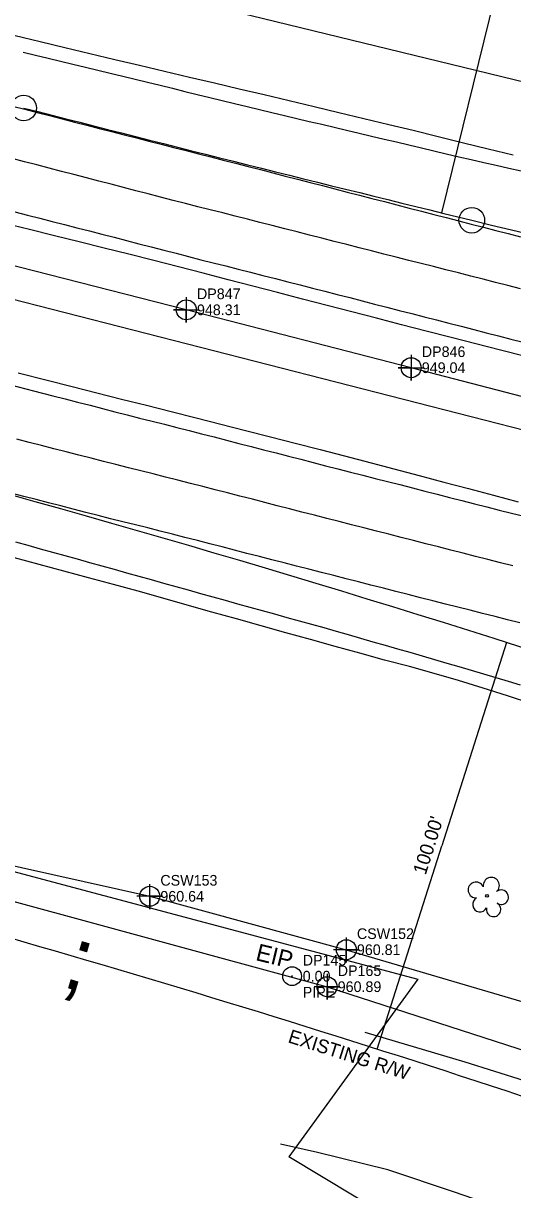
# Model space of a CAD drawing. Extents: x 1182322 to 1186765, y 572295 to 575411.
# Drawn here: x 1183432.3 to 1183547, y 574148.9 to 574422.2 of the extents above; entities that cross this region are included whole.
import ezdxf

# ---------------------------------------------------------------- set-up
doc = ezdxf.new("R2010")
doc.units = 0
for name, color, linetype in [('COGO Default Chain', 7, 'Continuous'), ('Exist Guardrail Cable Guide Rail', 7, 'Continuous'), ('Exist Guardrail Cable Guide Rail Cogo Elevation', 7, 'Continuous'), ('Exist Guardrail Cable Guide Rail Cogo Number', 7, 'Continuous'), ('Exist Guardrail Cable Guide Rail Cogo Point CELL', 7, 'Continuous'), ('Exist Horizontal Alignment', 7, 'Continuous'), ('Exist Horizontal Alignment Point', 7, 'Continuous'), ('Exist Other Culture Fence Line', 7, 'Continuous'), ('Exist Other Culture Fence Line Cogo Elevation', 7, 'Continuous'), ('Exist Other Culture Fence Line Cogo Number', 7, 'Continuous'), ('Exist Other Culture Fence Line Cogo Point CELL', 7, 'Continuous'), ('Exist Property Iron Pin CELL', 7, 'Continuous'), ('Exist Property Iron Pin Cogo Comment', 7, 'Continuous'), ('Exist Property Iron Pin Cogo Elevation', 7, 'Continuous'), ('Exist Property Iron Pin Cogo Number', 7, 'Continuous'), ('Exist Property Iron Pin Text', 7, 'Continuous'), ('Exist Right of Way Control of Access CA Symbol CELL', 7, 'Continuous'), ('Exist Right of Way Line', 7, 'Continuous'), ('Exist Right of Way Line Text', 7, 'Continuous'), ('Exist Right of Way Width CELL', 7, 'Continuous'), ('Exist Roads EOP', 7, 'Continuous'), ('Exist Roads EOT', 7, 'Continuous'), ('Exist Roads Soil', 7, 'Continuous'), ('Exist Structure Minor Pipes RCP 18 Inch', 7, 'Continuous'), ('Exist Utilities Telephone UG Conduit SUE LOS B', 7, 'Continuous'), ('Exist Utilities Telephone UG Conduit SUE LOS B Cogo Elevation', 7, 'Continuous'), ('Exist Utilities Telephone UG Conduit SUE LOS B Cogo Number', 7, 'Continuous'), ('Exist Utilities Telephone UG Conduit SUE LOS B Cogo Point CELL', 7, 'Continuous'), ('Exist Vegetation Tree CELL', 7, 'Continuous'), ('Sheet Layout Plan Border', 7, 'Continuous')]:
    doc.layers.add(name, color=color, linetype=linetype)

msp = doc.modelspace()

# ---------------------------------------------------------------- linework, layer by layer
at = {"layer": 'COGO Default Chain'}
msp.add_line((1182528.88, 574588.22), (1185362.14, 573862.9), dxfattribs=at)
for centre, radius, start, end in [((1186009.24, 584468.11), 10390.38, 255.640516, 256.23755), ((1183890.06, 575815.87), 1482.39, 256.23755, 268.02702), ((1182574.75, 571226.37), 3201.45, 68.49303, 75.64052)]:
    msp.add_arc(centre, radius, start, end, dxfattribs=at)
at = {"layer": 'Exist Guardrail Cable Guide Rail'}
msp.add_lwpolyline([(1183724.74, 574289.7), (1183677.28, 574301.88), (1183623.6, 574315.48), (1183573.41, 574328.42), (1183523.18, 574341.49), (1183470.48, 574355.05), (1183416.85, 574368.69), (1183366.96, 574381.41), (1183314.88, 574394.83), (1183262.33, 574408.3), (1183212.68, 574421.31), (1183161.26, 574434.27), (1183113.83, 574446.38), (1183064.43, 574459.18), (1183012.5, 574472.56), (1182962.1, 574485.47), (1182911.03, 574498.69), (1182859.7, 574511.98), (1182808.96, 574524.96), (1182757.01, 574537.77), (1182704.44, 574551.53), (1182655.16, 574564.04), (1182603.29, 574577.2), (1182552.65, 574589.83)], dxfattribs=at)
at = {"layer": 'Exist Guardrail Cable Guide Rail Cogo Point CELL'}
for points in [[(1183470.48, 574358.05), (1183470.48, 574352.05), (1183470.48, 574355.05), (1183467.48, 574355.05), (1183473.48, 574355.05)], [(1183523.18, 574344.49), (1183523.18, 574338.49), (1183523.18, 574341.49), (1183520.18, 574341.49), (1183526.18, 574341.49)]]:
    msp.add_lwpolyline(points, dxfattribs=at)
for centre in [(1183470.48, 574355.05), (1183523.18, 574341.49)]:
    msp.add_circle(centre, 2.34, dxfattribs=at)
at = {"layer": 'Exist Horizontal Alignment'}
msp.add_line((1182528.88, 574588.22), (1185362.14, 573862.9), dxfattribs=at)
for centre, radius, start, end in [((1186009.24, 584468.11), 10390.38, 255.640516, 256.23755), ((1183890.06, 575815.87), 1482.39, 256.23755, 268.02702), ((1182574.75, 571226.37), 3201.45, 68.49303, 75.64052)]:
    msp.add_arc(centre, radius, start, end, dxfattribs=at)
at = {"layer": 'Exist Horizontal Alignment Point'}
for centre in [(1183432.37, 574402.34), (1183537.4, 574376.04)]:
    msp.add_circle(centre, 3, dxfattribs=at)
at = {"layer": 'Exist Other Culture Fence Line'}
msp.add_lwpolyline([(1182431.26, 574477.6), (1182493.19, 574461.53), (1182576.37, 574440.23), (1182660.35, 574418.61), (1182745.71, 574396.94), (1182831.35, 574374.93), (1182917.06, 574353.23), (1182998.89, 574331.88), (1183080.06, 574310.08), (1183166.11, 574287.18), (1183252.15, 574263.83), (1183335.82, 574241.7), (1183417.69, 574219.73), (1183503.47, 574196.43), (1183592.65, 574167.54), (1183679.28, 574135.7), (1183764.86, 574099.44), (1183841.01, 574057.63), (1183931.32, 574004.09)], dxfattribs=at)
at = {"layer": 'Exist Other Culture Fence Line Cogo Point CELL'}
msp.add_lwpolyline([(1183503.47, 574199.43), (1183503.47, 574193.43), (1183503.47, 574196.43), (1183506.47, 574196.43), (1183500.47, 574196.43)], dxfattribs=at)
msp.add_circle((1183503.47, 574196.43), 2.34, dxfattribs=at)
at = {"layer": 'Exist Property Iron Pin CELL'}
for radius in [2.2, 0.0707]:
    msp.add_circle((1183495.27, 574198.89), radius, dxfattribs=at)
at = {"layer": 'Exist Right of Way Control of Access CA Symbol CELL'}
msp.add_line((1183450.28, 574201.67), (1183450.28, 574201.67), dxfattribs=at)
at = {"layer": 'Exist Right of Way Line'}
msp.add_arc((1182574.75, 571226.37), 3101.45, 71.1212, 75.64052, dxfattribs=at)
at = {"layer": 'Exist Right of Way Width CELL'}
for p, q in [((1183530.41, 574377.75), (1183543.63, 574431.59)), ((1183545.56, 574277.07), (1183530.4, 574229.44)), ((1183515.23, 574181.78), (1183530.4, 574229.44))]:
    msp.add_line(p, q, dxfattribs=at)
at = {"layer": 'Exist Roads EOP'}
for points in [[(1183430.34, 574419.3), (1183436.2, 574417.91), (1183442.04, 574416.52), (1183447.87, 574415.13), (1183453.71, 574413.74), (1183459.55, 574412.36), (1183465.39, 574410.98), (1183471.23, 574409.61), (1183477.07, 574408.23), (1183482.91, 574406.86), (1183488.75, 574405.48), (1183494.59, 574404.1), (1183500.42, 574402.7), (1183506.25, 574401.31), (1183512.08, 574399.91), (1183517.92, 574398.51), (1183523.66, 574397.12), (1183529.55, 574395.67), (1183535.44, 574394.22), (1183541.23, 574392.8), (1183547.06, 574391.4)], [(1183549.98, 574344.13), (1183544.16, 574345.62), (1183538.35, 574347.11), (1183532.54, 574348.59), (1183526.73, 574350.08), (1183520.91, 574351.56), (1183515.1, 574353.06), (1183509.3, 574354.56), (1183503.49, 574356.07), (1183497.68, 574357.58), (1183491.88, 574359.09), (1183486.07, 574360.6), (1183480.26, 574362.11), (1183474.46, 574363.62), (1183468.65, 574365.13), (1183462.84, 574366.63), (1183457.02, 574368.08), (1183451.19, 574369.52), (1183445.37, 574370.96), (1183439.55, 574372.4), (1183433.72, 574373.84), (1183427.9, 574375.29)], [(1183431.1, 574340.32), (1183437.89, 574338.59), (1183443.7, 574337.1), (1183449.51, 574335.61), (1183455.33, 574334.14), (1183461.14, 574332.68), (1183466.96, 574331.21), (1183472.78, 574329.73), (1183478.59, 574328.25), (1183484.39, 574326.76), (1183490.19, 574325.28), (1183496, 574323.8), (1183501.82, 574322.31), (1183507.6, 574320.83), (1183513.8, 574319.22), (1183519.1, 574317.81), (1183525.07, 574316.22), (1183530.84, 574314.69), (1183536.65, 574313.14), (1183542.45, 574311.6), (1183548.25, 574310.07)], [(1183551.47, 574262.74), (1183545.76, 574264.59), (1183540.04, 574266.4), (1183534.31, 574268.17), (1183528.55, 574269.85), (1183522.76, 574271.43), (1183516.96, 574272.98), (1183511.18, 574274.57), (1183505.4, 574276.17), (1183499.61, 574277.77), (1183493.83, 574279.36), (1183488.05, 574280.97), (1183482.27, 574282.6), (1183476.5, 574284.22), (1183470.72, 574285.84), (1183464.95, 574287.47), (1183459.17, 574289.09), (1183453.38, 574290.66), (1183447.59, 574292.23), (1183441.8, 574293.79), (1183436, 574295.36), (1183430.21, 574296.93)]]:
    msp.add_lwpolyline(points, dxfattribs=at)
at = {"layer": 'Exist Roads EOT'}
for points in [[(1183432.25, 574415.45), (1183435.16, 574414.74), (1183438.08, 574414.03), (1183440.99, 574413.31), (1183443.9, 574412.59), (1183446.82, 574411.88), (1183449.73, 574411.18), (1183452.65, 574410.48), (1183455.57, 574409.78), (1183458.49, 574409.08), (1183461.4, 574408.37), (1183464.32, 574407.67), (1183467.23, 574406.97), (1183470.15, 574406.25), (1183473.06, 574405.54), (1183475.98, 574404.83), (1183478.89, 574404.13), (1183481.81, 574403.42), (1183484.73, 574402.72), (1183487.64, 574402.02), (1183490.56, 574401.32), (1183493.48, 574400.62), (1183496.4, 574399.92), (1183499.31, 574399.22), (1183502.23, 574398.53), (1183505.15, 574397.83), (1183508.07, 574397.14), (1183510.99, 574396.45), (1183513.91, 574395.76), (1183516.83, 574395.07), (1183519.75, 574394.38), (1183522.67, 574393.7), (1183525.59, 574393.01), (1183528.51, 574392.32), (1183531.43, 574391.63), (1183534.35, 574390.94), (1183537.27, 574390.27), (1183540.2, 574389.6), (1183543.12, 574388.93), (1183546.05, 574388.27), (1183548.97, 574387.61)], [(1183429.73, 574402.79), (1183432.64, 574402.04), (1183435.54, 574401.29), (1183438.45, 574400.55), (1183441.35, 574399.8), (1183444.26, 574399.05), (1183447.16, 574398.31), (1183450.07, 574397.57), (1183452.98, 574396.83), (1183455.88, 574396.08), (1183458.79, 574395.34), (1183461.7, 574394.6), (1183464.6, 574393.86), (1183467.51, 574393.11), (1183470.42, 574392.37), (1183473.32, 574391.63), (1183476.23, 574390.88), (1183479.14, 574390.14), (1183482.04, 574389.4), (1183484.95, 574388.66), (1183487.86, 574387.91), (1183490.76, 574387.16), (1183493.67, 574386.41), (1183496.57, 574385.66), (1183499.48, 574384.91), (1183502.38, 574384.16), (1183505.28, 574383.41), (1183508.19, 574382.66), (1183511.09, 574381.91), (1183514, 574381.16), (1183516.9, 574380.41), (1183519.81, 574379.66), (1183522.71, 574378.91), (1183525.62, 574378.16), (1183528.52, 574377.41), (1183531.43, 574376.66), (1183534.33, 574375.91), (1183537.23, 574375.15), (1183540.14, 574374.4), (1183543.04, 574373.65), (1183545.95, 574372.9), (1183548.85, 574372.14)], [(1183548.78, 574359.97), (1183545.87, 574360.72), (1183542.97, 574361.46), (1183540.06, 574362.21), (1183537.15, 574362.95), (1183534.25, 574363.69), (1183531.34, 574364.43), (1183528.43, 574365.17), (1183525.52, 574365.91), (1183522.62, 574366.64), (1183519.71, 574367.38), (1183516.8, 574368.12), (1183513.89, 574368.86), (1183510.99, 574369.6), (1183508.08, 574370.34), (1183505.17, 574371.08), (1183502.26, 574371.82), (1183499.36, 574372.56), (1183496.45, 574373.3), (1183493.54, 574374.04), (1183490.64, 574374.78), (1183487.73, 574375.52), (1183484.82, 574376.26), (1183481.91, 574377), (1183479.01, 574377.74), (1183476.1, 574378.48), (1183473.19, 574379.22), (1183470.28, 574379.96), (1183467.38, 574380.7), (1183464.47, 574381.44), (1183461.57, 574382.2), (1183458.66, 574382.95), (1183455.76, 574383.71), (1183452.86, 574384.46), (1183449.95, 574385.22), (1183447.05, 574385.97), (1183444.15, 574386.73), (1183441.24, 574387.48), (1183438.34, 574388.24), (1183435.44, 574388.99), (1183432.53, 574389.75), (1183429.63, 574390.5)], [(1183430.32, 574377.98), (1183433.22, 574377.24), (1183436.13, 574376.5), (1183439.04, 574375.76), (1183441.94, 574375.02), (1183444.85, 574374.27), (1183447.76, 574373.53), (1183450.66, 574372.79), (1183453.57, 574372.04), (1183456.47, 574371.29), (1183459.38, 574370.55), (1183462.28, 574369.8), (1183465.19, 574369.04), (1183468.09, 574368.29), (1183471, 574367.54), (1183473.9, 574366.8), (1183476.81, 574366.06), (1183479.72, 574365.33), (1183482.63, 574364.59), (1183485.53, 574363.85), (1183488.44, 574363.11), (1183491.35, 574362.37), (1183494.26, 574361.63), (1183497.17, 574360.89), (1183500.07, 574360.15), (1183502.98, 574359.4), (1183505.88, 574358.65), (1183508.79, 574357.91), (1183511.69, 574357.16), (1183514.6, 574356.41), (1183517.5, 574355.67), (1183520.41, 574354.92), (1183523.31, 574354.17), (1183526.22, 574353.42), (1183529.13, 574352.68), (1183532.03, 574351.93), (1183534.94, 574351.19), (1183537.84, 574350.44), (1183540.75, 574349.69), (1183543.65, 574348.93), (1183546.56, 574348.18), (1183549.46, 574347.44)], [(1183429.27, 574337.44), (1183434.65, 574336.06), (1183439.2, 574334.91), (1183442.11, 574334.16), (1183445.01, 574333.42), (1183447.92, 574332.67), (1183450.82, 574331.93), (1183453.73, 574331.18), (1183456.64, 574330.44), (1183459.54, 574329.69), (1183462.45, 574328.96), (1183465.36, 574328.23), (1183468.27, 574327.5), (1183471.18, 574326.76), (1183474.08, 574326.01), (1183476.99, 574325.26), (1183479.89, 574324.51), (1183482.8, 574323.76), (1183485.7, 574323.01), (1183488.61, 574322.27), (1183491.51, 574321.52), (1183494.42, 574320.77), (1183497.32, 574320.02), (1183500.23, 574319.27), (1183503.13, 574318.51), (1183506.03, 574317.76), (1183508.94, 574317.01), (1183511.85, 574316.28), (1183514.76, 574315.55), (1183517.67, 574314.82), (1183520.57, 574314.08), (1183523.48, 574313.33), (1183526.38, 574312.58), (1183529.29, 574311.83), (1183532.2, 574311.09), (1183535.1, 574310.34), (1183538.01, 574309.59), (1183540.92, 574308.86), (1183543.83, 574308.13), (1183546.74, 574307.4), (1183549.64, 574306.66)], [(1183547.01, 574295.04), (1183544.1, 574295.78), (1183541.19, 574296.52), (1183538.29, 574297.26), (1183535.38, 574298), (1183532.47, 574298.74), (1183529.56, 574299.48), (1183526.66, 574300.22), (1183523.75, 574300.97), (1183520.84, 574301.71), (1183517.94, 574302.45), (1183515.03, 574303.19), (1183512.12, 574303.93), (1183509.22, 574304.68), (1183506.31, 574305.42), (1183503.4, 574306.17), (1183500.5, 574306.91), (1183497.59, 574307.66), (1183494.69, 574308.41), (1183491.78, 574309.15), (1183488.88, 574309.9), (1183485.97, 574310.65), (1183483.06, 574311.39), (1183480.16, 574312.14), (1183477.25, 574312.88), (1183474.35, 574313.63), (1183471.44, 574314.37), (1183468.53, 574315.11), (1183465.62, 574315.85), (1183462.72, 574316.59), (1183459.81, 574317.32), (1183456.9, 574318.06), (1183453.99, 574318.8), (1183451.09, 574319.54), (1183448.18, 574320.28), (1183445.27, 574321.02), (1183442.36, 574321.75), (1183439.46, 574322.49), (1183436.55, 574323.23), (1183433.64, 574323.97), (1183430.73, 574324.72)], [(1183548.65, 574281.68), (1183545.75, 574282.42), (1183542.84, 574283.16), (1183539.93, 574283.9), (1183537.02, 574284.64), (1183534.12, 574285.37), (1183531.21, 574286.11), (1183528.3, 574286.85), (1183525.39, 574287.59), (1183522.49, 574288.33), (1183519.58, 574289.07), (1183516.67, 574289.81), (1183513.76, 574290.55), (1183510.86, 574291.29), (1183507.95, 574292.03), (1183505.04, 574292.77), (1183502.14, 574293.51), (1183499.23, 574294.25), (1183496.32, 574294.99), (1183493.41, 574295.74), (1183490.51, 574296.48), (1183487.6, 574297.23), (1183484.7, 574297.98), (1183481.79, 574298.72), (1183478.89, 574299.47), (1183475.98, 574300.22), (1183473.08, 574300.97), (1183470.17, 574301.72), (1183467.27, 574302.47), (1183464.36, 574303.2), (1183461.45, 574303.93), (1183458.54, 574304.65), (1183455.62, 574305.37), (1183452.71, 574306.1), (1183449.81, 574306.84), (1183446.9, 574307.59), (1183444, 574308.34), (1183441.09, 574309.09), (1183438.19, 574309.84), (1183435.28, 574310.58), (1183432.37, 574311.31), (1183429.46, 574312.05)], [(1183430.42, 574300.66), (1183433.31, 574299.86), (1183436.21, 574299.06), (1183439.1, 574298.27), (1183441.99, 574297.47), (1183444.88, 574296.67), (1183447.77, 574295.87), (1183450.66, 574295.06), (1183453.55, 574294.26), (1183456.44, 574293.45), (1183459.33, 574292.64), (1183462.22, 574291.84), (1183465.11, 574291.03), (1183468, 574290.22), (1183470.89, 574289.41), (1183473.78, 574288.6), (1183476.67, 574287.79), (1183479.56, 574286.99), (1183482.45, 574286.18), (1183485.34, 574285.38), (1183488.23, 574284.58), (1183491.12, 574283.78), (1183494.01, 574282.98), (1183496.9, 574282.18), (1183499.79, 574281.38), (1183502.68, 574280.57), (1183505.57, 574279.76), (1183508.45, 574278.93), (1183511.34, 574278.11), (1183514.22, 574277.28), (1183517.11, 574276.45), (1183519.99, 574275.63), (1183522.87, 574274.8), (1183525.76, 574273.97), (1183528.64, 574273.13), (1183531.51, 574272.28), (1183534.39, 574271.43), (1183537.27, 574270.58), (1183540.14, 574269.72), (1183543.02, 574268.87), (1183545.89, 574268.01), (1183548.77, 574267.16)]]:
    msp.add_lwpolyline(points, dxfattribs=at)
at = {"layer": 'Exist Roads Soil'}
for points in [[(1183512.29, 574185.81), (1183535.79, 574178.82), (1183563.6, 574170.07), (1183591.37, 574160.95), (1183609.09, 574155.07), (1183628.38, 574147.71), (1183647.44, 574140.74), (1183665.14, 574134.14), (1183687.91, 574125.98), (1183706.67, 574118.53), (1183725.88, 574111.44), (1183744.64, 574103.16), (1183762.37, 574094.18)], [(1183574.11, 574103.43), (1183587.76, 574101.54), (1183613.58, 574093.91), (1183626.46, 574089.82), (1183638.78, 574087.24), (1183647.24, 574087.43), (1183651.81, 574088.88), (1183655.92, 574092.16), (1183659.78, 574095.82), (1183662.01, 574098.88), (1183662.47, 574101.25), (1183662.11, 574101.87), (1183660.73, 574102.96), (1183654.05, 574106.18), (1183641.44, 574110.26), (1183625.15, 574116.37), (1183610.23, 574121.78), (1183588.85, 574129.38), (1183571.98, 574134.95), (1183555.27, 574140.7), (1183533.31, 574148.28), (1183517.74, 574153.49), (1183501.26, 574157.61), (1183492.55, 574159.49)]]:
    msp.add_lwpolyline(points, dxfattribs=at)
at = {"layer": 'Exist Structure Minor Pipes RCP 18 Inch'}
msp.add_line((1183631.8, 574388.34), (1183307.11, 574467.53), dxfattribs=at)
at = {"layer": 'Exist Utilities Telephone UG Conduit SUE LOS B'}
msp.add_lwpolyline([(1183184.2, 574290.24), (1183230.46, 574277.8), (1183276.74, 574264.86), (1183322.88, 574252.13), (1183369.36, 574239.84), (1183416.41, 574227.82), (1183461.9, 574217.61), (1183507.97, 574205.1), (1183555.78, 574190.97), (1183600.29, 574174.7), (1183642.38, 574158.78), (1183685.83, 574141.54), (1183729.44, 574124.53), (1183772.61, 574105.48), (1183815.48, 574084.72), (1183856.9, 574064.89), (1183910.26, 574040.72), (1183938.65, 574025.64), (1184017.13, 573974.93), (1184056.25, 573949.51), (1184095.95, 573918.75), (1184120.25, 573896.12), (1184153.18, 573876.37), (1184177.6, 573863.32)], dxfattribs=at)
at = {"layer": 'Exist Utilities Telephone UG Conduit SUE LOS B Cogo Point CELL'}
for points in [[(1183461.88, 574220.42), (1183461.92, 574214.61), (1183461.9, 574217.61), (1183464.92, 574217.61), (1183458.92, 574217.61)], [(1183507.95, 574207.92), (1183507.99, 574202.1), (1183507.97, 574205.1), (1183510.99, 574205.1), (1183504.99, 574205.1)]]:
    msp.add_lwpolyline(points, dxfattribs=at)
for centre in [(1183461.92, 574217.61), (1183507.99, 574205.1)]:
    msp.add_circle(centre, 2.34, dxfattribs=at)
at = {"layer": 'Exist Vegetation Tree CELL'}
msp.add_line((1183540.96, 574217.73), (1183540.96, 574217.73), dxfattribs=at)
msp.add_circle((1183540.96, 574217.73), 0.326, dxfattribs=at)
for centre, radius, start, end in [((1183538.4, 574219.09), 1.86, 24.5374, 274.0857), ((1183541.97, 574220.14), 1.9, 311.4735, 188.5723), ((1183544.29, 574217.4), 1.7, 235.6545, 128.9324), ((1183539.32, 574215.7), 1.73, 117.036, 333.7181), ((1183542.51, 574214.53), 1.69, 165.9394, 60.6034)]:
    msp.add_arc(centre, radius, start, end, dxfattribs=at)
at = {"layer": 'Sheet Layout Plan Border'}
for p, q in [((1183012.24, 574334.8), (1183524.74, 574198.18)), ((1183524.74, 574198.18), (1183494.54, 574156.56)), ((1184011.14, 573845.69), (1183494.54, 574156.56))]:
    msp.add_line(p, q, dxfattribs=at)

# ---------------------------------------------------------------- texts
at = {"layer": 'Exist Guardrail Cable Guide Rail Cogo Elevation'}
for s, p in [('948.31', (1183472.98, 574353.8)), ('949.04', (1183525.68, 574340.24))]:
    msp.add_text(s, height=2.5, dxfattribs=at).set_placement(p)
at = {"layer": 'Exist Guardrail Cable Guide Rail Cogo Number'}
for s, p in [('DP847', (1183472.98, 574357.55)), ('DP846', (1183525.68, 574343.99))]:
    msp.add_text(s, height=2.5, dxfattribs=at).set_placement(p)
at = {"layer": 'Exist Other Culture Fence Line Cogo Elevation'}
msp.add_text('960.89', height=2.5, dxfattribs=at).set_placement((1183505.97, 574195.18))
at = {"layer": 'Exist Other Culture Fence Line Cogo Number'}
msp.add_text('DP165', height=2.5, dxfattribs=at).set_placement((1183505.97, 574198.93))
at = {"layer": 'Exist Property Iron Pin Cogo Comment'}
msp.add_text('PIPE', height=2.5, dxfattribs=at).set_placement((1183497.77, 574193.89))
at = {"layer": 'Exist Property Iron Pin Cogo Elevation'}
msp.add_text('0.00', height=2.5, dxfattribs=at).set_placement((1183497.77, 574197.64))
at = {"layer": 'Exist Property Iron Pin Cogo Number'}
msp.add_text('DP145', height=2.5, dxfattribs=at).set_placement((1183497.77, 574201.39))
at = {"layer": 'Exist Property Iron Pin Text'}
msp.add_text('EIP', height=4, rotation=346.2681, dxfattribs=at).set_placement((1183486.54, 574202.69))
at = {"layer": 'Exist Right of Way Control of Access CA Symbol CELL'}
msp.add_text(';', height=15, rotation=343.6025, dxfattribs=at).set_placement((1183440.97, 574196.59))
at = {"layer": 'Exist Right of Way Line Text'}
msp.add_text('EXISTING R/W', height=3.2, rotation=342.435, dxfattribs=at).set_placement((1183494.12, 574183.44))
at = {"layer": 'Exist Right of Way Width CELL'}
msp.add_text("100.00'", height=3.2, rotation=72.3476, dxfattribs=at).set_placement((1183526.58, 574222.46))
at = {"layer": 'Exist Utilities Telephone UG Conduit SUE LOS B Cogo Elevation'}
for s, p in [('960.64', (1183464.4, 574216.36)), ('960.81', (1183510.47, 574203.85))]:
    msp.add_text(s, height=2.5, dxfattribs=at).set_placement(p)
at = {"layer": 'Exist Utilities Telephone UG Conduit SUE LOS B Cogo Number'}
for s, p in [('CSW153', (1183464.4, 574220.11)), ('CSW152', (1183510.47, 574207.6))]:
    msp.add_text(s, height=2.5, dxfattribs=at).set_placement(p)

doc.saveas('drawing.dxf')
